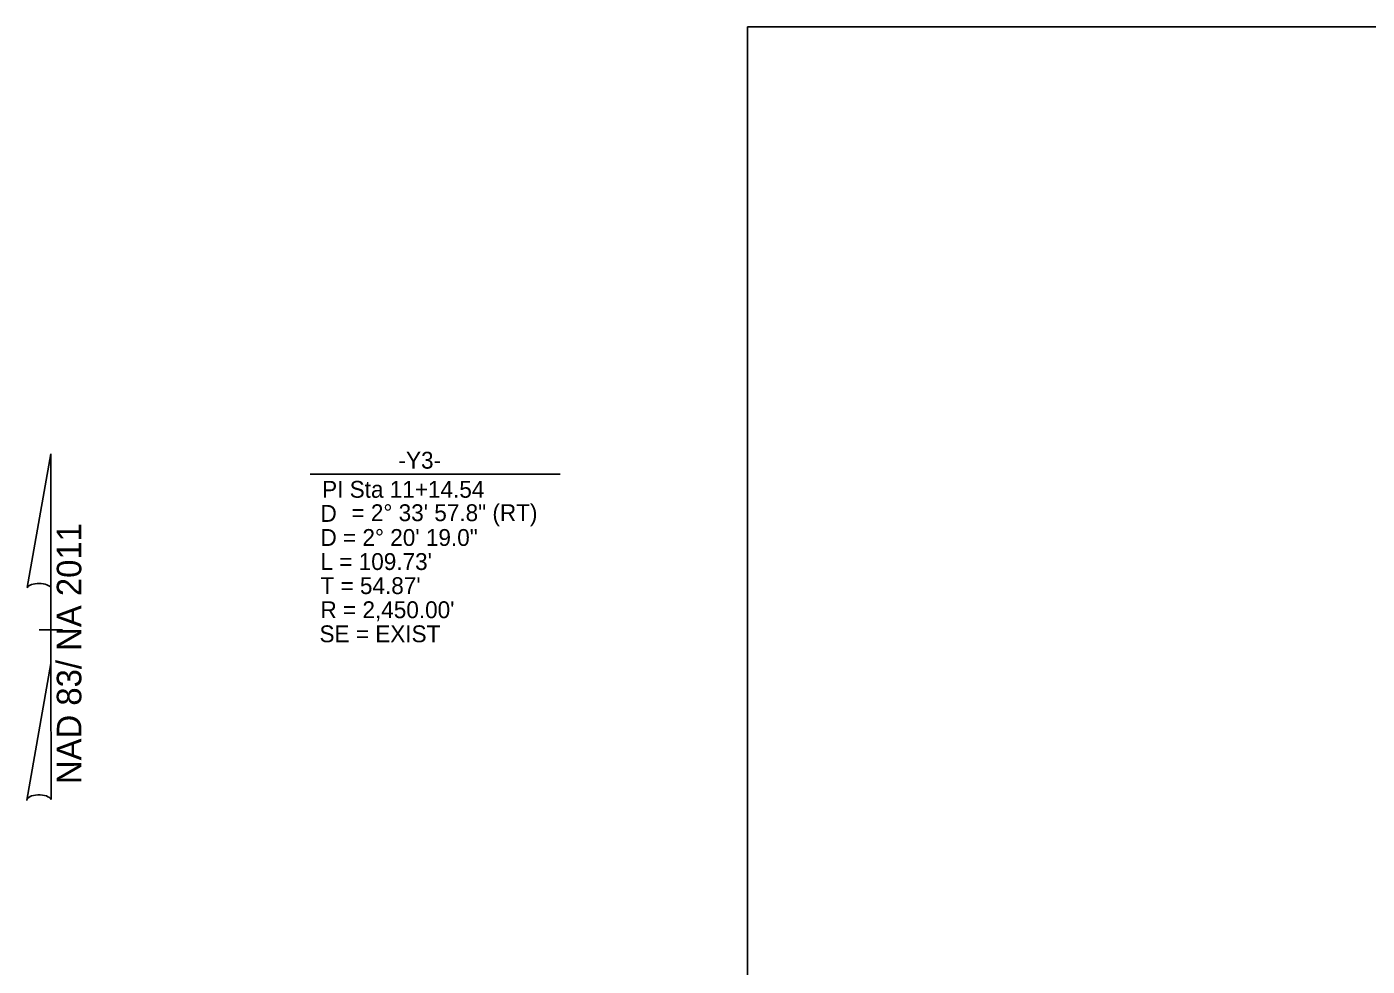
# Model space of a CAD drawing. Extents: x 1755545 to 1761252, y 736169 to 737766.
# Drawn here: x 1758823 to 1759380, y 737376 to 737766 of the extents above; entities that cross this region are included whole.
import ezdxf

# ---------------------------------------------------------------- set-up
doc = ezdxf.new("R2010")
doc.units = 0
for name, color, linetype in [('Prop Horizontal Alignment Curve and Spiral Data', 7, 'Continuous'), ('Prop North Arrow NAD83 for Plan Sheets CELL', 7, 'Continuous'), ('Scratch_Level_5', 7, 'Continuous')]:
    doc.layers.add(name, color=color, linetype=linetype)

msp = doc.modelspace()

# ---------------------------------------------------------------- linework, layer by layer
at = {"layer": 'Prop Horizontal Alignment Curve and Spiral Data'}
msp.add_line((1758940.61, 737580.15), (1759044.51, 737580.15), dxfattribs=at)
at = {"layer": 'Prop North Arrow NAD83 for Plan Sheets CELL'}
for p, q in [((1758823.08, 737532.98), (1758832.92, 737588.6)), ((1758832.98, 737588.6), (1758832.92, 737588.6)), ((1758832.98, 737588.6), (1758832.92, 737588.6)), ((1758832.98, 737588.6), (1758832.98, 737531.24)), ((1758832.98, 737501.48), (1758832.98, 737532.92)), ((1758832.98, 737531.24), (1758832.98, 737532.86)), ((1758828.18, 737515.4), (1758828.12, 737515.4)), ((1758832.44, 737515.4), (1758828.18, 737515.4)), ((1758828.24, 737515.4), (1758837.84, 737515.4)), ((1758832.98, 737501.48), (1758822.96, 737444.78)), ((1758833.04, 737445.02), (1758832.98, 737501.48))]:
    msp.add_line(p, q, dxfattribs=at)
for centre, start_param, end_param in [((1758828.05, 737532.38), 0.216388, 2.908219), ((1758828.05, 737444.58), 0.201328, 3.141593)]:
    msp.add_ellipse(centre, major_axis=(5.08, -0.04), ratio=0.461098, start_param=start_param, end_param=end_param, dxfattribs=at)
at = {"layer": 'Scratch_Level_5'}
msp.add_lwpolyline([(1759122.38, 737765.89), (1760563.07, 737765.89), (1760563.07, 736805.42), (1759122.38, 736805.42)], close=True, dxfattribs=at)

# ---------------------------------------------------------------- texts
at = {"layer": 'Prop Horizontal Alignment Curve and Spiral Data'}
for s, p in [('-Y3-', (1758977.36, 737582.39)), ('PI Sta 11+14.54', (1758945.64, 737570.3)), ('D', (1758944.96, 737560.3)), ('= 2%%d 33\' 57.8" (RT)', (1758957.81, 737560.59)), ('D = 2%%d 20\' 19.0"', (1758944.96, 737550.3)), ("L = 109.73'", (1758944.96, 737540.3)), ("T = 54.87'", (1758944.96, 737530.3)), ("R = 2,450.00'", (1758944.96, 737520.3)), ('SE = EXIST', (1758944.55, 737510.3))]:
    msp.add_text(s, height=7, dxfattribs=at).set_placement(p)
at = {"layer": 'Prop North Arrow NAD83 for Plan Sheets CELL'}
msp.add_text('NAD 83/ NA 2011', height=10.2, rotation=90, dxfattribs=at).set_placement((1758845.61, 737451.37))

doc.saveas('drawing.dxf')
